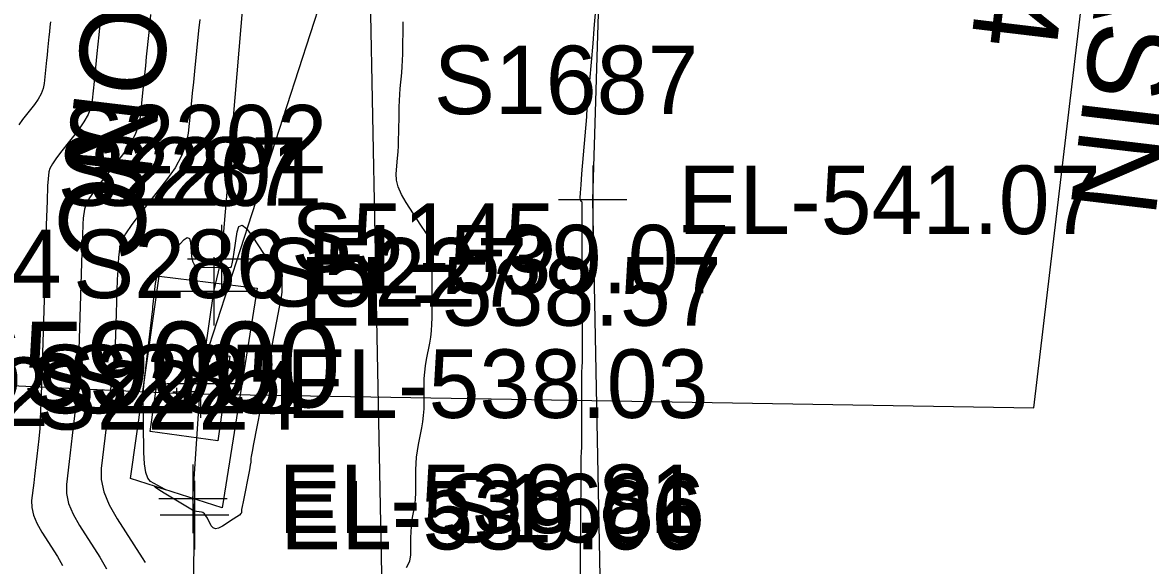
# Model space of a CAD drawing. Extents: x 1724534 to 1727318, y 657156 to 660047.
# Drawn here: x 1725514.8 to 1725580.7, y 658993.3 to 659025 of the extents above; entities that cross this region are included whole.
import ezdxf

# ---------------------------------------------------------------- set-up
doc = ezdxf.new("R2010")
doc.units = 0
for name, color, linetype in [('SURVEY - CONTOURS - Index with Text', 7, 'Continuous'), ('SURVEY - CONTOURS - Intermediate with optional Text', 7, 'Continuous'), ('SURVEY - CONTROL - Grid Text', 7, 'Continuous'), ('SURVEY - DRAINAGE - Storm Sewer', 7, 'Continuous'), ('SURVEY - DRAINAGE - Storm Sewer - Points - Locators', 7, 'Continuous'), ('SURVEY - DRAINAGE - Storm Sewer - Points - Numbers', 7, 'Continuous'), ('SURVEY - DRAINAGE - Storm Sewer Text', 7, 'Continuous'), ('SURVEY - DTM - Breaklines', 7, 'Continuous'), ('SURVEY - DTM - Breaklines - Points - Elevations', 7, 'Continuous'), ('SURVEY - DTM - Breaklines - Points - Locators', 7, 'Continuous'), ('SURVEY - DTM - Breaklines - Points - Numbers', 7, 'Continuous'), ('SURVEY - MISCELLANEOUS - Bottom of MH and CB', 7, 'Continuous'), ('SURVEY - MISCELLANEOUS - Bottom of MH and CB - Points - Numbers', 7, 'Continuous'), ('SURVEY - NON-TRANSPORTATION - Features', 7, 'Continuous'), ('SURVEY - NON-TRANSPORTATION - Features Text', 7, 'Continuous'), ('SURVEY - TRANSPORTATION - Features', 7, 'Continuous'), ('SURVEY - TRANSPORTATION - Features - Points - Elevations', 7, 'Continuous'), ('SURVEY - TRANSPORTATION - Features - Points - Locators', 7, 'Continuous'), ('SURVEY - TRANSPORTATION - Features - Points - Numbers', 7, 'Continuous'), ('SURVEY - UTILITIES - Fiber Optic Cable (Underground) with Text', 7, 'Continuous')]:
    doc.layers.add(name, color=color, linetype=linetype)

msp = doc.modelspace()

# ---------------------------------------------------------------- linework, layer by layer
at = {"layer": 'SURVEY - CONTOURS - Index with Text'}
for points in [[(1725525.123, 659025.156), (1725525.056, 659024.509), (1725524.814, 659022.139), (1725524.748, 659021.495), (1725524.682, 659020.853), (1725524.617, 659020.212), (1725524.442, 659018.505), (1725524.313, 659017.855), (1725524.059, 659017.183), (1725523.678, 659016.491), (1725523.171, 659015.777), (1725521.65, 659013.846), (1725521.148, 659013.182), (1725520.781, 659012.637), (1725520.549, 659012.211), (1725520.454, 659011.905), (1725520.379, 659011.249), (1725520.352, 659010.943), (1725520.326, 659010.516), (1725520.303, 659009.968), (1725520.281, 659009.299), (1725520.226, 659007.354), (1725520.198, 659006.64), (1725520.158, 659005.956), (1725520.105, 659005.302), (1725520.039, 659004.677), (1725519.846, 659003.052), (1725519.773, 659002.442), (1725519.7, 659001.828), (1725519.356, 658998.935), (1725519.36, 658998.285), (1725519.519, 658997.577), (1725519.832, 658996.811), (1725520.301, 658995.987), (1725521.758, 658993.713), (1725521.923, 658993.432)], [(1725537.205, 658993.156), (1725537.401, 658993.513), (1725537.466, 658993.881), (1725537.467, 658994.874), (1725537.473, 658995.228), (1725537.49, 658995.544), (1725537.517, 658995.821), (1725537.556, 658996.06), (1725537.673, 658996.647), (1725537.711, 658996.887), (1725537.738, 658997.166), (1725537.755, 658997.485), (1725537.761, 658997.842), (1725537.761, 658998.848), (1725537.77, 658999.223), (1725537.797, 658999.595), (1725537.842, 658999.964), (1725537.905, 659000.329), (1725538.096, 659001.297), (1725538.158, 659001.663), (1725538.203, 659002.033), (1725538.23, 659002.408), (1725538.239, 659002.788), (1725538.238, 659003.807), (1725538.247, 659004.186), (1725538.273, 659004.56), (1725538.317, 659004.927), (1725538.378, 659005.288), (1725538.565, 659006.244), (1725538.626, 659006.606), (1725538.67, 659006.975), (1725538.696, 659007.352), (1725538.704, 659007.735), (1725538.702, 659009.544), (1725538.701, 659009.933), (1725538.7, 659011.365), (1725538.699, 659011.707), (1725538.699, 659011.952), (1725538.699, 659012.099), (1725538.699, 659012.148), (1725538.699, 659012.15), (1725538.658, 659012.213), (1725538.537, 659012.399), (1725538.335, 659012.708), (1725538.053, 659013.14), (1725537.192, 659014.458), (1725536.914, 659014.933), (1725536.723, 659015.372), (1725536.62, 659015.773), (1725536.606, 659016.138), (1725536.685, 659017.06), (1725536.712, 659017.413), (1725536.732, 659017.781), (1725536.747, 659018.162), (1725536.756, 659018.558), (1725536.773, 659019.633), (1725536.782, 659020.029), (1725536.797, 659020.41), (1725536.818, 659020.776), (1725536.844, 659021.127), (1725536.924, 659022.044), (1725536.951, 659022.396), (1725536.971, 659022.763), (1725536.986, 659023.145), (1725536.995, 659023.543), (1725537.01, 659024.623), (1725537.018, 659025.02)]]:
    msp.add_lwpolyline(points, dxfattribs=at)
at = {"layer": 'SURVEY - CONTOURS - Intermediate with optional Text'}
for points in [[(1725547.372, 658991.415), (1725547.375, 658993.924), (1725547.378, 658994.374), (1725547.381, 658994.653), (1725547.385, 658994.761), (1725547.396, 658994.82), (1725547.4, 658994.928), (1725547.403, 658995.209), (1725547.405, 658995.663), (1725547.406, 658996.289), (1725547.407, 658998.189), (1725547.408, 658998.817), (1725547.411, 658999.274), (1725547.415, 658999.562), (1725547.421, 658999.681), (1725547.438, 658999.77), (1725547.444, 658999.888), (1725547.448, 659000.178), (1725547.45, 659000.638), (1725547.451, 659003.809), (1725547.453, 659004.267), (1725547.456, 659004.555), (1725547.461, 659004.67), (1725547.477, 659004.75), (1725547.482, 659004.866), (1725547.485, 659005.154), (1725547.487, 659006.249), (1725547.484, 659008.889), (1725547.481, 659011.061), (1725547.477, 659014.454), (1725547.477, 659014.458), (1725547.474, 659014.463), (1725547.466, 659014.476), (1725547.434, 659014.525), (1725547.378, 659014.611), (1725547.367, 659014.731), (1725547.378, 659015.025), (1725547.409, 659015.493), (1725547.461, 659016.135), (1725547.745, 659019.468), (1725547.753, 659019.574), (1725547.753, 659019.62), (1725547.826, 659020.484), (1725548.108, 659023.751), (1725548.18, 659024.597), (1725548.181, 659024.617), (1725548.51, 659028.4)], [(1725522.248, 659025.442), (1725522.194, 659024.912), (1725522.14, 659024.383), (1725521.996, 659022.974), (1725521.942, 659022.446), (1725521.888, 659021.919), (1725521.834, 659021.394), (1725521.78, 659020.87), (1725521.638, 659019.475), (1725521.533, 659018.943), (1725521.324, 659018.394), (1725521.013, 659017.828), (1725520.598, 659017.245), (1725519.355, 659015.666), (1725518.944, 659015.123), (1725518.645, 659014.677), (1725518.455, 659014.33), (1725518.377, 659014.079), (1725518.316, 659013.543), (1725518.291, 659013.189), (1725518.261, 659012.53), (1725518.227, 659011.566), (1725518.189, 659010.297), (1725518.081, 659006.505), (1725518.038, 659005.199), (1725517.99, 659004.124), (1725517.938, 659003.281), (1725517.881, 659002.67), (1725517.724, 659001.348), (1725517.665, 659000.851), (1725517.606, 659000.352), (1725517.546, 658999.85), (1725517.486, 658999.346), (1725517.326, 658997.999), (1725517.329, 658997.47), (1725517.458, 658996.894), (1725517.713, 658996.271), (1725518.095, 658995.601), (1725519.28, 658993.751), (1725519.677, 658993.072)], [(1725516.397, 659025.012), (1725516.367, 659024.718), (1725516.337, 659024.424), (1725516.307, 659024.131), (1725516.227, 659023.351), (1725516.197, 659023.059), (1725516.168, 659022.767), (1725516.029, 659021.414), (1725515.971, 659021.12), (1725515.856, 659020.816), (1725515.683, 659020.503), (1725515.454, 659020.18), (1725514.766, 659019.306), (1725514.538, 659019.005)], [(1725519.308, 659025.08), (1725519.223, 659024.257), (1725519.111, 659023.162), (1725519.07, 659022.752), (1725519.028, 659022.343), (1725518.986, 659021.935), (1725518.944, 659021.529), (1725518.833, 659020.445), (1725518.752, 659020.032), (1725518.59, 659019.605), (1725518.348, 659019.165), (1725518.026, 659018.712), (1725517.06, 659017.486), (1725516.741, 659017.064), (1725516.508, 659016.718), (1725516.361, 659016.448), (1725516.301, 659016.254), (1725516.253, 659015.837), (1725516.23, 659015.436), (1725516.196, 659014.545), (1725516.152, 659013.165), (1725516.097, 659011.295), (1725515.935, 659005.656), (1725515.877, 659003.758), (1725515.822, 659002.293), (1725515.771, 659001.261), (1725515.724, 659000.662), (1725515.603, 658999.644), (1725515.465, 658998.49), (1725515.419, 658998.101), (1725515.296, 658997.063), (1725515.298, 658996.655), (1725515.398, 658996.212), (1725515.594, 658995.731), (1725515.888, 658995.215), (1725516.801, 658993.789), (1725517.108, 658993.266)], [(1725521.807, 659003.302), (1725521.808, 659003.315), (1725521.873, 659003.967), (1725522.285, 659007.433), (1725522.36, 659008.094), (1725522.371, 659008.204), (1725522.373, 659008.301), (1725522.378, 659008.369), (1725522.413, 659008.696), (1725522.53, 659009.731), (1725522.595, 659010.032), (1725522.725, 659010.352), (1725522.918, 659010.691), (1725523.176, 659011.049), (1725523.948, 659012.03), (1725524.204, 659012.312), (1725524.394, 659012.425), (1725524.518, 659012.369), (1725524.576, 659012.142), (1725524.642, 659011.311), (1725524.694, 659011.038), (1725524.799, 659010.843), (1725524.957, 659010.725), (1725525.169, 659010.684), (1725526.943, 659010.668), (1725526.977, 659010.723), (1725527.021, 659010.89), (1725527.073, 659011.169), (1725527.134, 659011.559), (1725527.31, 659012.747), (1725527.414, 659013.066), (1725527.594, 659013.131), (1725527.851, 659012.943), (1725528.185, 659012.5), (1725529.921, 659009.843), (1725529.921, 659009.221), (1725529.905, 659009.088), (1725529.854, 659008.796), (1725529.77, 659008.346), (1725529.178, 659005.299), (1725529.094, 659004.852), (1725529.043, 659004.564), (1725529.027, 659004.436), (1725529.027, 659004.308), (1725529.01, 659004.179), (1725528.958, 659003.889), (1725528.873, 659003.437), (1725528.269, 659000.365), (1725528.184, 658999.916), (1725528.133, 658999.63), (1725528.115, 658999.507), (1725528.115, 658999.395), (1725528.105, 658999.306), (1725528.074, 658999.123), (1725528.022, 658998.846), (1725527.654, 658996.989), (1725527.602, 658996.713), (1725527.571, 658996.533), (1725527.56, 658996.447), (1725527.56, 658996.346), (1725527.53, 658996.294), (1725527.441, 658996.214), (1725527.292, 658996.104), (1725527.083, 658995.966), (1725526.446, 658995.56), (1725526.226, 658995.448), (1725526.045, 658995.415), (1725525.902, 658995.461), (1725525.798, 658995.586), (1725525.572, 658996.027), (1725525.486, 658996.173), (1725525.399, 658996.281), (1725525.31, 658996.351), (1725525.219, 658996.383), (1725524.79, 658996.444), (1725523.044, 658997.499), (1725522.732, 658997.692), (1725522.544, 658997.819), (1725522.48, 658997.88), (1725522.54, 658997.875), (1725523.108, 658997.695), (1725522.25, 658998.18), (1725522.088, 658998.363), (1725521.969, 658998.703), (1725521.894, 658999.201), (1725521.862, 658999.857), (1725521.813, 659003.196), (1725521.811, 659003.29), (1725521.807, 659003.3), (1725521.807, 659003.302)]]:
    msp.add_lwpolyline(points, dxfattribs=at)
at = {"layer": 'SURVEY - DRAINAGE - Storm Sewer'}
for p, q in [((1725525.462, 659005.406), (1725554.556, 659095.327)), ((1725451.141, 659006.707), (1725524.546, 659003.293)), ((1725524.546, 659003.293), (1725524.546, 659003.293))]:
    msp.add_line(p, q, dxfattribs=at)
msp.add_lwpolyline([(1725526.175, 659000.537), (1725522.215, 659001.098), (1725522.917, 659006.049), (1725526.877, 659005.488), (1725526.175, 659000.537)], dxfattribs=at)
at = {"layer": 'SURVEY - DRAINAGE - Storm Sewer - Points - Locators'}
for p, q in [((1725525.462, 659005.156), (1725525.462, 659005.656)), ((1725525.712, 659005.406), (1725525.212, 659005.406)), ((1725525.462, 659005.406), (1725525.462, 659005.406)), ((1725525.462, 659005.406), (1725525.462, 659005.406)), ((1725523.79, 659003.138), (1725523.79, 659003.638)), ((1725524.04, 659003.388), (1725523.54, 659003.388)), ((1725523.79, 659003.388), (1725523.79, 659003.388)), ((1725523.79, 659003.388), (1725523.79, 659003.388))]:
    msp.add_line(p, q, dxfattribs=at)
at = {"layer": 'SURVEY - DRAINAGE - Storm Sewer Text'}
msp.add_lwpolyline([(1725524.546, 659003.293), (1725573.878, 659002.473), (1725580.472, 659058.246)], dxfattribs=at)
at = {"layer": 'SURVEY - DTM - Breaklines'}
for points in [[(1725525.942, 659009.271), (1725526.399, 659011.158), (1725528.918, 659041.105), (1725531.461, 659071.052), (1725534.8, 659101.37), (1725536.346, 659131.334), (1725539.898, 659161.171), (1725544.971, 659191.09), (1725550.75, 659220.691), (1725554.674, 659250.537), (1725558.308, 659280.317), (1725560.346, 659299.038), (1725563.922, 659328.825), (1725567.992, 659357.481)], [(1725524.72, 658997.154), (1725525.169, 659003.883), (1725525.942, 659009.271)], [(1725533.454, 658738.584), (1725529.91, 658768.444), (1725528.895, 658798.433), (1725528.35, 658828.444), (1725532.274, 658858.683), (1725531.303, 658888.673), (1725527.687, 658918.53), (1725523.837, 658948.374), (1725524.63, 658981.767), (1725524.814, 658996.206), (1725524.72, 658997.154)]]:
    msp.add_lwpolyline(points, dxfattribs=at)
at = {"layer": 'SURVEY - DTM - Breaklines - Points - Locators'}
for p, q in [((1725526.399, 659013.158), (1725526.399, 659009.158)), ((1725528.399, 659011.158), (1725524.399, 659011.158)), ((1725525.942, 659011.271), (1725525.942, 659007.271)), ((1725525.942, 659011.271), (1725525.942, 659007.271)), ((1725527.942, 659009.271), (1725523.942, 659009.271)), ((1725527.942, 659009.271), (1725523.942, 659009.271)), ((1725525.169, 659005.883), (1725525.169, 659001.883)), ((1725527.169, 659003.883), (1725523.169, 659003.883)), ((1725524.72, 658999.154), (1725524.72, 658995.154)), ((1725524.72, 658999.154), (1725524.72, 658995.154)), ((1725524.814, 658998.206), (1725524.814, 658994.206)), ((1725526.72, 658997.154), (1725522.72, 658997.154)), ((1725526.72, 658997.154), (1725522.72, 658997.154)), ((1725526.814, 658996.206), (1725522.814, 658996.206))]:
    msp.add_line(p, q, dxfattribs=at)
at = {"layer": 'SURVEY - MISCELLANEOUS - Bottom of MH and CB'}
for p, q in [((1725524.413, 659002.914), (1725524.413, 659003.914)), ((1725524.913, 659003.414), (1725523.913, 659003.414)), ((1725524.413, 659003.414), (1725524.413, 659003.414)), ((1725524.413, 659003.414), (1725524.413, 659003.414))]:
    msp.add_line(p, q, dxfattribs=at)
at = {"layer": 'SURVEY - NON-TRANSPORTATION - Features'}
msp.add_lwpolyline([(1725526.441, 658996.625), (1725521.073, 658998.349), (1725522.755, 659010.155), (1725528.481, 659009.465), (1725526.441, 658996.625)], dxfattribs=at)
at = {"layer": 'SURVEY - TRANSPORTATION - Features'}
msp.add_lwpolyline([(1725548.733, 658939.305), (1725548.535, 658964.315), (1725548.579, 658989.617), (1725548.091, 659014.622), (1725548.852, 659039.619), (1725549.567, 659064.874), (1725549.301, 659089.91), (1725550.369, 659114.889), (1725551.556, 659139.862), (1725552.642, 659165.042), (1725554.694, 659189.961), (1725556.721, 659214.883), (1725558.747, 659239.804), (1725561.49, 659264.678)], dxfattribs=at)
at = {"layer": 'SURVEY - TRANSPORTATION - Features - Points - Locators'}
for p, q in [((1725548.091, 659016.622), (1725548.091, 659012.622)), ((1725550.091, 659014.622), (1725546.091, 659014.622))]:
    msp.add_line(p, q, dxfattribs=at)
at = {"layer": 'SURVEY - UTILITIES - Fiber Optic Cable (Underground) with Text'}
msp.add_line((1725538.949, 658827.551), (1725533.816, 659093.214), dxfattribs=at)

# ---------------------------------------------------------------- texts
at = {"layer": 'SURVEY - CONTROL - Grid Text'}
msp.add_text(' N 659000 ', height=5, dxfattribs=at).set_placement((1725502.5, 659002.5))
at = {"layer": 'SURVEY - DRAINAGE - Storm Sewer - Points - Numbers'}
for s, p in [('S5145', (1725530.462, 659010.406)), ('S2044', (1725501.593, 659008.883)), ('S5227', (1725528.79, 659008.388))]:
    msp.add_text(s, height=4, dxfattribs=at).set_placement(p)
at = {"layer": 'SURVEY - DRAINAGE - Storm Sewer Text'}
for s, p in [('TOP-538.24', (1725574.517, 659059.937)), ('CATCH BASIN', (1725581.328, 659058.746))]:
    msp.add_text(s, height=5, rotation=263.19502, dxfattribs=at).set_placement(p)
at = {"layer": 'SURVEY - DTM - Breaklines - Points - Elevations'}
for s, p in [('EL-539.07', (1725531.399, 659009.158)), ('EL-538.57', (1725530.942, 659007.271)), ('EL-538.57', (1725530.942, 659007.271)), ('EL-538.03', (1725530.169, 659001.883)), ('EL-538.81', (1725529.72, 658995.154)), ('EL-538.81', (1725529.72, 658995.154)), ('EL-539.06', (1725529.814, 658994.206))]:
    msp.add_text(s, height=4, dxfattribs=at).set_placement(p)
at = {"layer": 'SURVEY - DTM - Breaklines - Points - Numbers'}
for s, p in [('S2202', (1725517.111, 659016.158)), ('S2201', (1725516.812, 659014.271)), ('S287', (1725518.606, 659014.271)), ('S286', (1725517.723, 659008.883)), ('S2225', (1725515.432, 659002.154)), ('S285', (1725517.384, 659002.154)), ('S2224', (1725515.526, 659001.206))]:
    msp.add_text(s, height=4, dxfattribs=at).set_placement(p)
at = {"layer": 'SURVEY - MISCELLANEOUS - Bottom of MH and CB - Points - Numbers'}
msp.add_text('S8002', height=4, dxfattribs=at).set_placement((1725500.838, 659001.414))
at = {"layer": 'SURVEY - NON-TRANSPORTATION - Features Text'}
msp.add_text('CONC', height=5, rotation=263.19502, dxfattribs=at).set_placement((1725519.022, 659031.016))
at = {"layer": 'SURVEY - TRANSPORTATION - Features - Points - Elevations'}
msp.add_text('EL-541.07', height=4, dxfattribs=at).set_placement((1725553.091, 659012.622))
at = {"layer": 'SURVEY - TRANSPORTATION - Features - Points - Numbers'}
for s, p in [('S1687', (1725538.803, 659019.622)), ('S1686', (1725539.181, 658994.617))]:
    msp.add_text(s, height=4, dxfattribs=at).set_placement(p)

doc.saveas('drawing.dxf')
